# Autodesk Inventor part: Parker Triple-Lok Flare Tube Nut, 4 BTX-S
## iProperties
Shininess: 20.0
Length Units: 11272
Angle Units: 11279
Time Units: 11290
Mass Units: 11286
Length Display Precision: 3
Angle Display Precision: 2
Created: 2001-09
Part Number: Parker Triple-Lok Flare Tube Nut, 4 BTX-S
Material: Stainless Steel, Austenitic
Description: Parker Triple-Lok Flare Tube Nut, 4 BTX-S
Document SubType Name: Modeling
Designer: jhagarty
Density: 0.0
Volumn: 0.0
Area: 0.0
PropertySet Name: Model Information
Control State: 0
Master: False
Checked Out: False
Last Check In By: Charles Bliss
Last Check In Date: 2003-09-27
Author: jhagarty
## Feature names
1. Extrusion1
2. Revolution1
3. Mirror1
4. Hole1
5. Hole2
6. Chamfer2
